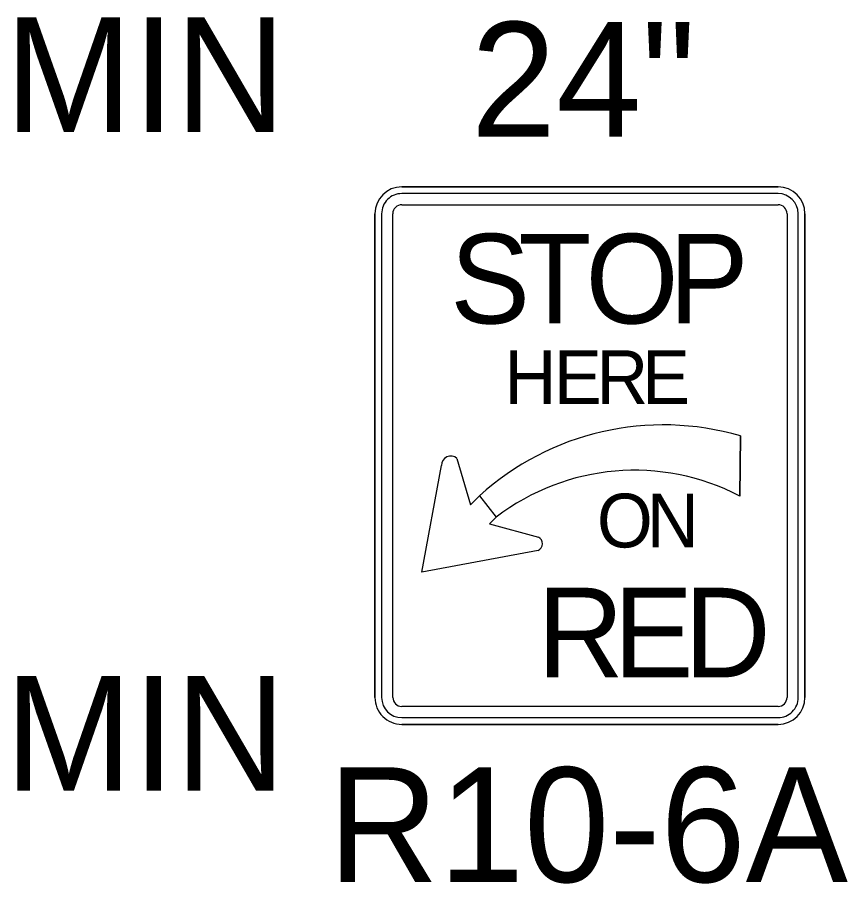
# Model space of a CAD drawing. Extents: x 99999.1 to 100095.7, y 99995 to 100010.7.
# Drawn here: x 100043.877 to 100044.456, y 100004.851 to 100005.456 of the extents above; entities that cross this region are included whole.
import ezdxf

# ---------------------------------------------------------------- set-up
doc = ezdxf.new("R2010")
doc.units = 0
doc.layers.add('TR_SN_ConstructionSigns', color=7, linetype='Continuous')

msp = doc.modelspace()

# ---------------------------------------------------------------- linework, layer by layer
at = {"layer": 'TR_SN_ConstructionSigns'}
for p, q in [((100044.4079, 100005.33733), (100044.1454, 100005.33733)), ((100044.1454, 100005.33733), (100044.4079, 100005.33733)), ((100044.4079, 100005.33733), (100044.1454, 100005.33733)), ((100044.1454, 100005.33733), (100044.4079, 100005.33733)), ((100044.4079, 100005.33264), (100044.1454, 100005.33264)), ((100044.1454, 100005.32483), (100044.4079, 100005.32483)), ((100044.12665, 100005.31858), (100044.12665, 100004.98108)), ((100044.12665, 100004.98108), (100044.12665, 100005.31858)), ((100044.12665, 100005.31858), (100044.12665, 100004.98108)), ((100044.12665, 100004.98108), (100044.12665, 100005.31858)), ((100044.13134, 100005.31858), (100044.13134, 100004.98108)), ((100044.13915, 100004.98108), (100044.13915, 100005.31858)), ((100044.41415, 100005.31858), (100044.41415, 100004.98108)), ((100044.42196, 100004.98108), (100044.42196, 100005.31858)), ((100044.42665, 100004.98108), (100044.42665, 100005.31858)), ((100044.42665, 100005.31858), (100044.42665, 100004.98108)), ((100044.42665, 100004.98108), (100044.42665, 100005.31858)), ((100044.42665, 100005.31858), (100044.42665, 100004.98108)), ((100044.38162, 100005.16355), (100044.38127, 100005.12158)), ((100044.38127, 100005.12158), (100044.38162, 100005.16355)), ((100044.18388, 100005.14785), (100044.19332, 100005.11544)), ((100044.15946, 100005.06858), (100044.17306, 100005.14302)), ((100044.19332, 100005.11544), (100044.19964, 100005.12177)), ((100044.19964, 100005.12177), (100044.21134, 100005.10688)), ((100044.19964, 100005.12177), (100044.21134, 100005.10688)), ((100044.21134, 100005.10688), (100044.20659, 100005.10212)), ((100044.20659, 100005.10212), (100044.24078, 100005.09293)), ((100044.2406, 100005.08365), (100044.15946, 100005.06858)), ((100044.4079, 100004.97483), (100044.1454, 100004.97483)), ((100044.1454, 100004.96702), (100044.4079, 100004.96702)), ((100044.1454, 100004.96233), (100044.4079, 100004.96233)), ((100044.4079, 100004.96233), (100044.1454, 100004.96233)), ((100044.1454, 100004.96233), (100044.4079, 100004.96233)), ((100044.4079, 100004.96233), (100044.1454, 100004.96233))]:
    msp.add_line(p, q, dxfattribs=at)
for centre, radius, start, end in [((100044.1454, 100005.31858), 0.01875, 90, 180), ((100044.1454, 100005.31858), 0.01875, 90, 180), ((100044.1454, 100005.31858), 0.01875, 90, 180), ((100044.1454, 100005.31858), 0.01875, 90, 180), ((100044.4079, 100005.31858), 0.01875, 0, 90), ((100044.4079, 100005.31858), 0.01875, 0, 90), ((100044.4079, 100005.31858), 0.01875, 0, 90), ((100044.4079, 100005.31858), 0.01875, 0, 90), ((100044.1454, 100005.31858), 0.01406, 90, 180.00001), ((100044.4079, 100005.31858), 0.01406, 0, 90), ((100044.1454, 100005.31858), 0.00625, 90, 180.00001), ((100044.4079, 100005.31858), 0.00625, 0, 90), ((100044.32787, 100004.98042), 0.19085, 73.6434, 132.21315), ((100044.32787, 100004.98042), 0.19085, 73.6434, 132.21315), ((100044.30783, 100004.98102), 0.15859, 62.4149, 127.4769), ((100044.30783, 100004.98102), 0.15859, 62.4149, 127.4769), ((100044.1454, 100004.98108), 0.01875, 180, 270.00001), ((100044.1454, 100004.98108), 0.01875, 180, 270.00001), ((100044.1454, 100004.98108), 0.01875, 180, 270.00001), ((100044.1454, 100004.98108), 0.01875, 180, 270.00001), ((100044.1454, 100004.98108), 0.01406, 180.00001, 270), ((100044.1454, 100004.98108), 0.00625, 180.00001, 270), ((100044.4079, 100004.98108), 0.01875, 270.00001, 0.00001), ((100044.4079, 100004.98108), 0.01875, 270.00001, 0.00001), ((100044.4079, 100004.98108), 0.01875, 270.00001, 0.00001), ((100044.4079, 100004.98108), 0.01406, 270, 0.00001), ((100044.4079, 100004.98108), 0.00625, 270, 0.00001), ((100044.4079, 100004.98108), 0.01875, 270.00001, 0.00001)]:
    msp.add_arc(centre, radius, start, end, dxfattribs=at)
for centre, major_axis, ratio, start_param, end_param in [((100044.17953, 100005.1431), (-0.00647, -0.00009), 0.989437, 3.962549, 6.283185), ((100044.23839, 100005.08834), (-0.0046, 0.00239), 0.999053, 2.490568, 4.712389)]:
    msp.add_ellipse(centre, major_axis=major_axis, ratio=ratio, start_param=start_param, end_param=end_param, dxfattribs=at)

# ---------------------------------------------------------------- texts
for s, p in [('MIN', (100043.86842, 100005.37559)), ('24"', (100044.19357, 100005.37233)), ('MIN', (100043.86842, 100004.91597)), ('R10-6A', (100044.09395, 100004.85233))]:
    msp.add_text(s, height=0.08, rotation=360, dxfattribs=at).set_placement(p)
for s, height, p in [('S', 0.0625, (100044.17915, 100005.24202)), ('O', 0.0625, (100044.27353, 100005.24202)), ('T', 0.0625, (100044.22665, 100005.24202)), ('P', 0.0625, (100044.33165, 100005.24202)), ('H', 0.0375, (100044.21703, 100005.18577)), ('E', 0.0375, (100044.25153, 100005.18577)), ('R', 0.0375, (100044.28115, 100005.18577)), ('E', 0.0375, (100044.31303, 100005.18577)), ('O', 0.0375, (100044.28152, 100005.08577)), ('N', 0.0375, (100044.3164, 100005.08577)), ('R', 0.0625, (100044.23992, 100004.99514)), ('E', 0.0625, (100044.29305, 100004.99514)), ('D', 0.0625, (100044.34242, 100004.99514))]:
    msp.add_text(s, height=height, dxfattribs=at).set_placement(p)

doc.saveas('drawing.dxf')
